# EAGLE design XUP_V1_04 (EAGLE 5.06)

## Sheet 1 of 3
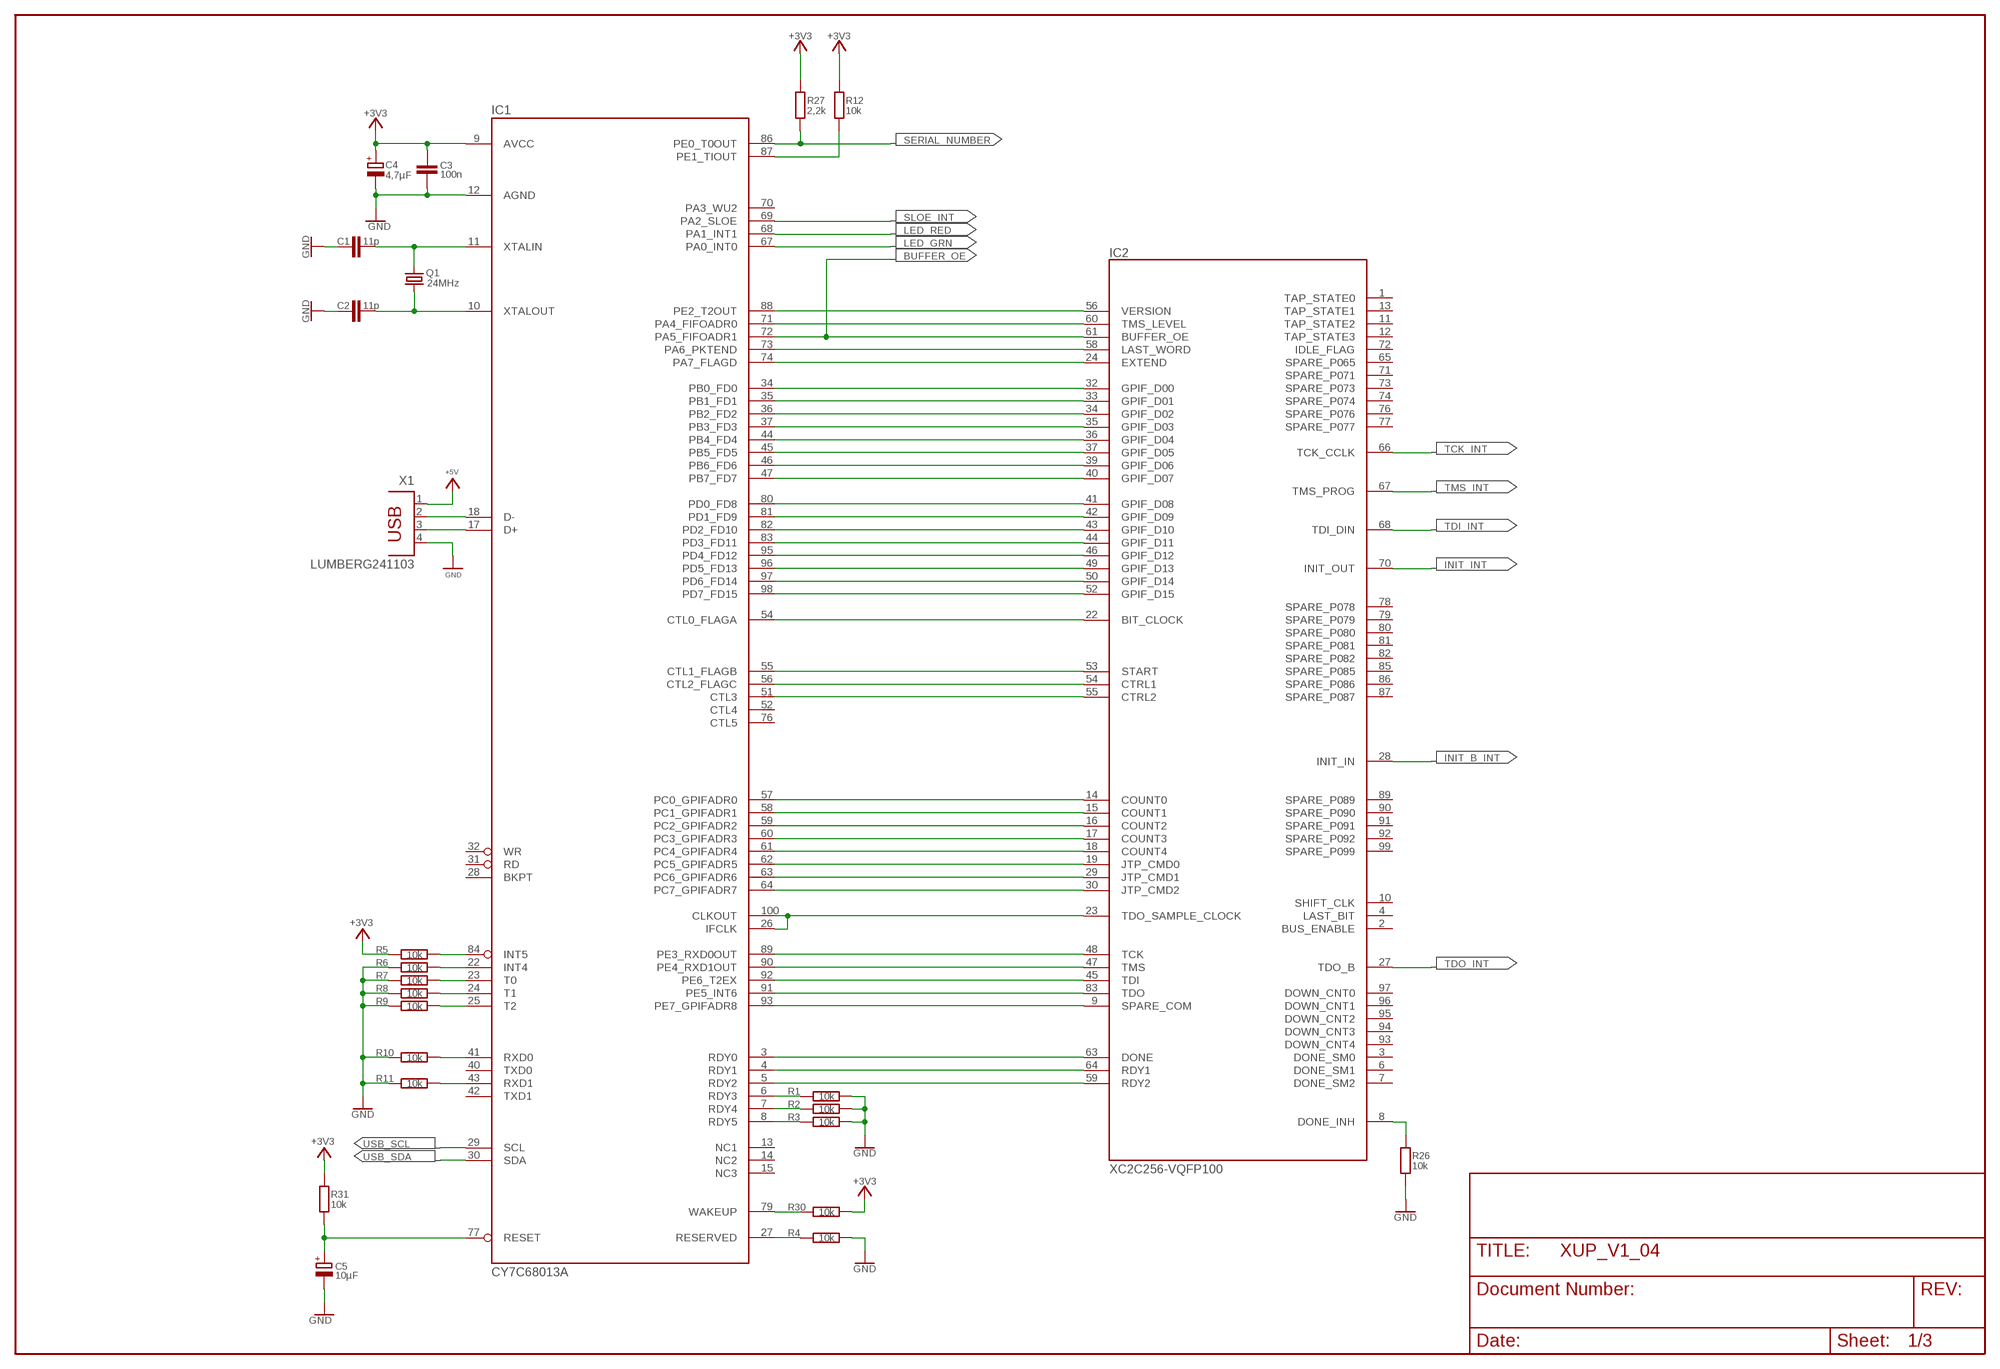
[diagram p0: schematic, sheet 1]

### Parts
C1  11p  C-EUALT  [0805ALT]
C2  11p  C-EUALT  [0805ALT]
C3  100n  C-EUC0603K  [C0603K]
C4  4,7µF  CPOL-EUB/3528-21R  [B/3528-21R]
C5  10µF  CPOL-EUB/3528-21R  [B/3528-21R]
IC1  CY7C68013A  [QFP100R]
IC2  XC2C256-VQFP100  [VQFP100]
Q1  24MHz  CRYTALHC49U-V  [HC49U-V]
R1  10k  R-EU_  [0805ALT]
R2  10k  R-EU_  [0805ALT]
R3  10k  R-EU_  [0805ALT]
R4  10k  R-EU_  [0805ALT]
R5  10k  R-EU_  [0805ALT]
R6  10k  R-EU_  [0805ALT]
R7  10k  R-EU_  [0805ALT]
R8  10k  R-EU_  [0805ALT]
R9  10k  R-EU_  [0805ALT]
R10  10k  R-EU_  [0805ALT]
R11  10k  R-EU_  [0805ALT]
R12  10k  R-EU_  [0805ALT]
R26  10k  R-EU_  [0805ALT]
R27  2,2k  R-EU_  [0805ALT]
R30  10k  R-EU_  [0805ALT]
R31  10k  R-EU_  [0805ALT]
X1  LUMBERG241103  [LUMBERG24110X]

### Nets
+3V3: C3.1 C4.+ IC1.9(AVCC) R5.1 R12.2 R27.2 R30.2 R31.2 ; also sheet 2,3
+5V: X1.1 ; also sheet 2
BUFFER_OE: IC1.72(PA5_FIFOADR1) IC2.61(BUFFER_OE) ; also sheet 3
GND: C1.1 C2.1 C3.2 C4.- C5.- IC1.12(AGND) R1.2 R2.2 R3.2 R4.2 R6.1 R7.1 R8.1 R9.1 R10.1 R11.1 R26.1 X1.4 ; also sheet 2,3
INIT_B_INT: IC2.28(INIT_IN) ; also sheet 3
INIT_INT: IC2.70(INIT_OUT) ; also sheet 3
LED_GRN: IC1.67(PA0_INT0) ; also sheet 2
LED_RED: IC1.68(PA1_INT1) ; also sheet 2
N$1: IC1.88(PE2_T2OUT) IC2.56(VERSION)
N$2: IC1.71(PA4_FIFOADR0) IC2.60(TMS_LEVEL)
N$3: IC1.18(D-) X1.2
N$4: IC1.73(PA6_PKTEND) IC2.58(LAST_WORD)
N$5: IC1.74(PA7_FLAGD) IC2.24(EXTEND)
N$6: IC1.34(PB0_FD0) IC2.32(GPIF_D00)
N$7: IC1.35(PB1_FD1) IC2.33(GPIF_D01)
N$8: IC1.36(PB2_FD2) IC2.34(GPIF_D02)
N$9: IC1.37(PB3_FD3) IC2.35(GPIF_D03)
N$10: IC1.44(PB4_FD4) IC2.36(GPIF_D04)
N$11: IC1.45(PB5_FD5) IC2.37(GPIF_D05)
N$12: IC1.46(PB6_FD6) IC2.39(GPIF_D06)
N$13: IC1.47(PB7_FD7) IC2.40(GPIF_D07)
N$14: IC1.80(PD0_FD8) IC2.41(GPIF_D08)
N$15: IC1.81(PD1_FD9) IC2.42(GPIF_D09)
N$16: IC1.82(PD2_FD10) IC2.43(GPIF_D10)
N$17: IC1.83(PD3_FD11) IC2.44(GPIF_D11)
N$18: IC1.95(PD4_FD12) IC2.46(GPIF_D12)
N$19: IC1.96(PD5_FD13) IC2.49(GPIF_D13)
N$20: IC1.97(PD6_FD14) IC2.50(GPIF_D14)
N$21: IC1.98(PD7_FD15) IC2.52(GPIF_D15)
N$22: IC1.54(CTL0_FLAGA) IC2.22(BIT_CLOCK)
N$23: IC1.55(CTL1_FLAGB) IC2.53(START)
N$24: IC1.56(CTL2_FLAGC) IC2.54(CTRL1)
N$25: IC1.51(CTL3) IC2.55(CTRL2)
N$26: IC1.57(PC0_GPIFADR0) IC2.14(COUNT0)
N$27: IC1.58(PC1_GPIFADR1) IC2.15(COUNT1)
N$28: IC1.59(PC2_GPIFADR2) IC2.16(COUNT2)
N$29: IC1.60(PC3_GPIFADR3) IC2.17(COUNT3)
N$30: IC1.61(PC4_GPIFADR4) IC2.18(COUNT4)
N$31: IC1.62(PC5_GPIFADR5) IC2.19(JTP_CMD0)
N$32: IC1.63(PC6_GPIFADR6) IC2.29(JTP_CMD1)
N$33: IC1.64(PC7_GPIFADR7) IC2.30(JTP_CMD2)
N$34: IC1.26(IFCLK) IC1.100(CLKOUT) IC2.23(TDO_SAMPLE_CLOCK)
N$35: IC1.89(PE3_RXD0OUT) IC2.48(TCK)
N$36: IC1.90(PE4_RXD1OUT) IC2.47(TMS)
N$37: IC1.92(PE6_T2EX) IC2.45(TDI)
N$38: IC1.91(PE5_INT6) IC2.83(TDO)
N$39: IC1.93(PE7_GPIFADR8) IC2.9(SPARE_COM)
N$40: IC1.3(RDY0) IC2.63(DONE)
N$41: IC1.4(RDY1) IC2.64(RDY1)
N$42: IC1.5(RDY2) IC2.59(RDY2)
N$43: IC1.84(INT5) R5.2
N$44: IC1.6(RDY3) R1.1
N$45: IC1.7(RDY4) R2.1
N$46: IC1.8(RDY5) R3.1
N$47: IC1.27(RESERVED) R4.1
N$48: IC1.22(INT4) R6.2
N$49: IC1.79(WAKEUP) R30.1
N$51: IC1.23(T0) R7.2
N$52: IC1.24(T1) R8.2
N$53: IC1.41(RXD0) R10.2
N$54: IC1.43(RXD1) R11.2
N$55: IC1.25(T2) R9.2
N$58: C1.2 IC1.11(XTALIN) Q1.2
N$59: C2.2 IC1.10(XTALOUT) Q1.1
N$60: IC1.87(PE1_TIOUT) R12.1
N$66: IC1.17(D+) X1.3
N$75: IC2.8(DONE_INH) R26.2
RST: C5.+ IC1.77(RESET) R31.1
SERIAL_NUMBER: IC1.86(PE0_T0OUT) R27.1 ; also sheet 2
SLOE_INT: IC1.69(PA2_SLOE) ; also sheet 3
TCK_INT: IC2.66(TCK_CCLK) ; also sheet 3
TDI_INT: IC2.68(TDI_DIN) ; also sheet 3
TDO_INT: IC2.27(TDO_B) ; also sheet 3
TMS_INT: IC2.67(TMS_PROG) ; also sheet 3
USB_SCL: IC1.29(SCL) ; also sheet 2
USB_SDA: IC1.30(SDA) ; also sheet 2
Unconnected: IC1.13(NC1) IC1.14(NC2) IC1.15(NC3) IC1.28(BKPT) IC1.31(RD) IC1.32(WR) IC1.40(TXD0) IC1.42(TXD1) IC1.52(CTL4) IC1.70(PA3_WU2) IC1.76(CTL5) IC2.1(TAP_STATE0) IC2.2(BUS_ENABLE) IC2.3(DONE_SM0) IC2.4(LAST_BIT) IC2.6(DONE_SM1) IC2.7(DONE_SM2) IC2.10(SHIFT_CLK) IC2.11(TAP_STATE2) IC2.12(TAP_STATE3) IC2.13(TAP_STATE1) IC2.65(SPARE_P065) IC2.71(SPARE_P071) IC2.72(IDLE_FLAG) IC2.73(SPARE_P073) IC2.74(SPARE_P074) IC2.76(SPARE_P076) IC2.77(SPARE_P077) IC2.78(SPARE_P078) IC2.79(SPARE_P079) IC2.80(SPARE_P080) IC2.81(SPARE_P081) IC2.82(SPARE_P082) IC2.85(SPARE_P085) IC2.86(SPARE_P086) IC2.87(SPARE_P087) IC2.89(SPARE_P089) IC2.90(SPARE_P090) IC2.91(SPARE_P091) IC2.92(SPARE_P092) IC2.93(DOWN_CNT4) IC2.94(DOWN_CNT3) IC2.95(DOWN_CNT2) IC2.96(DOWN_CNT1) IC2.97(DOWN_CNT0) IC2.99(SPARE_P099)

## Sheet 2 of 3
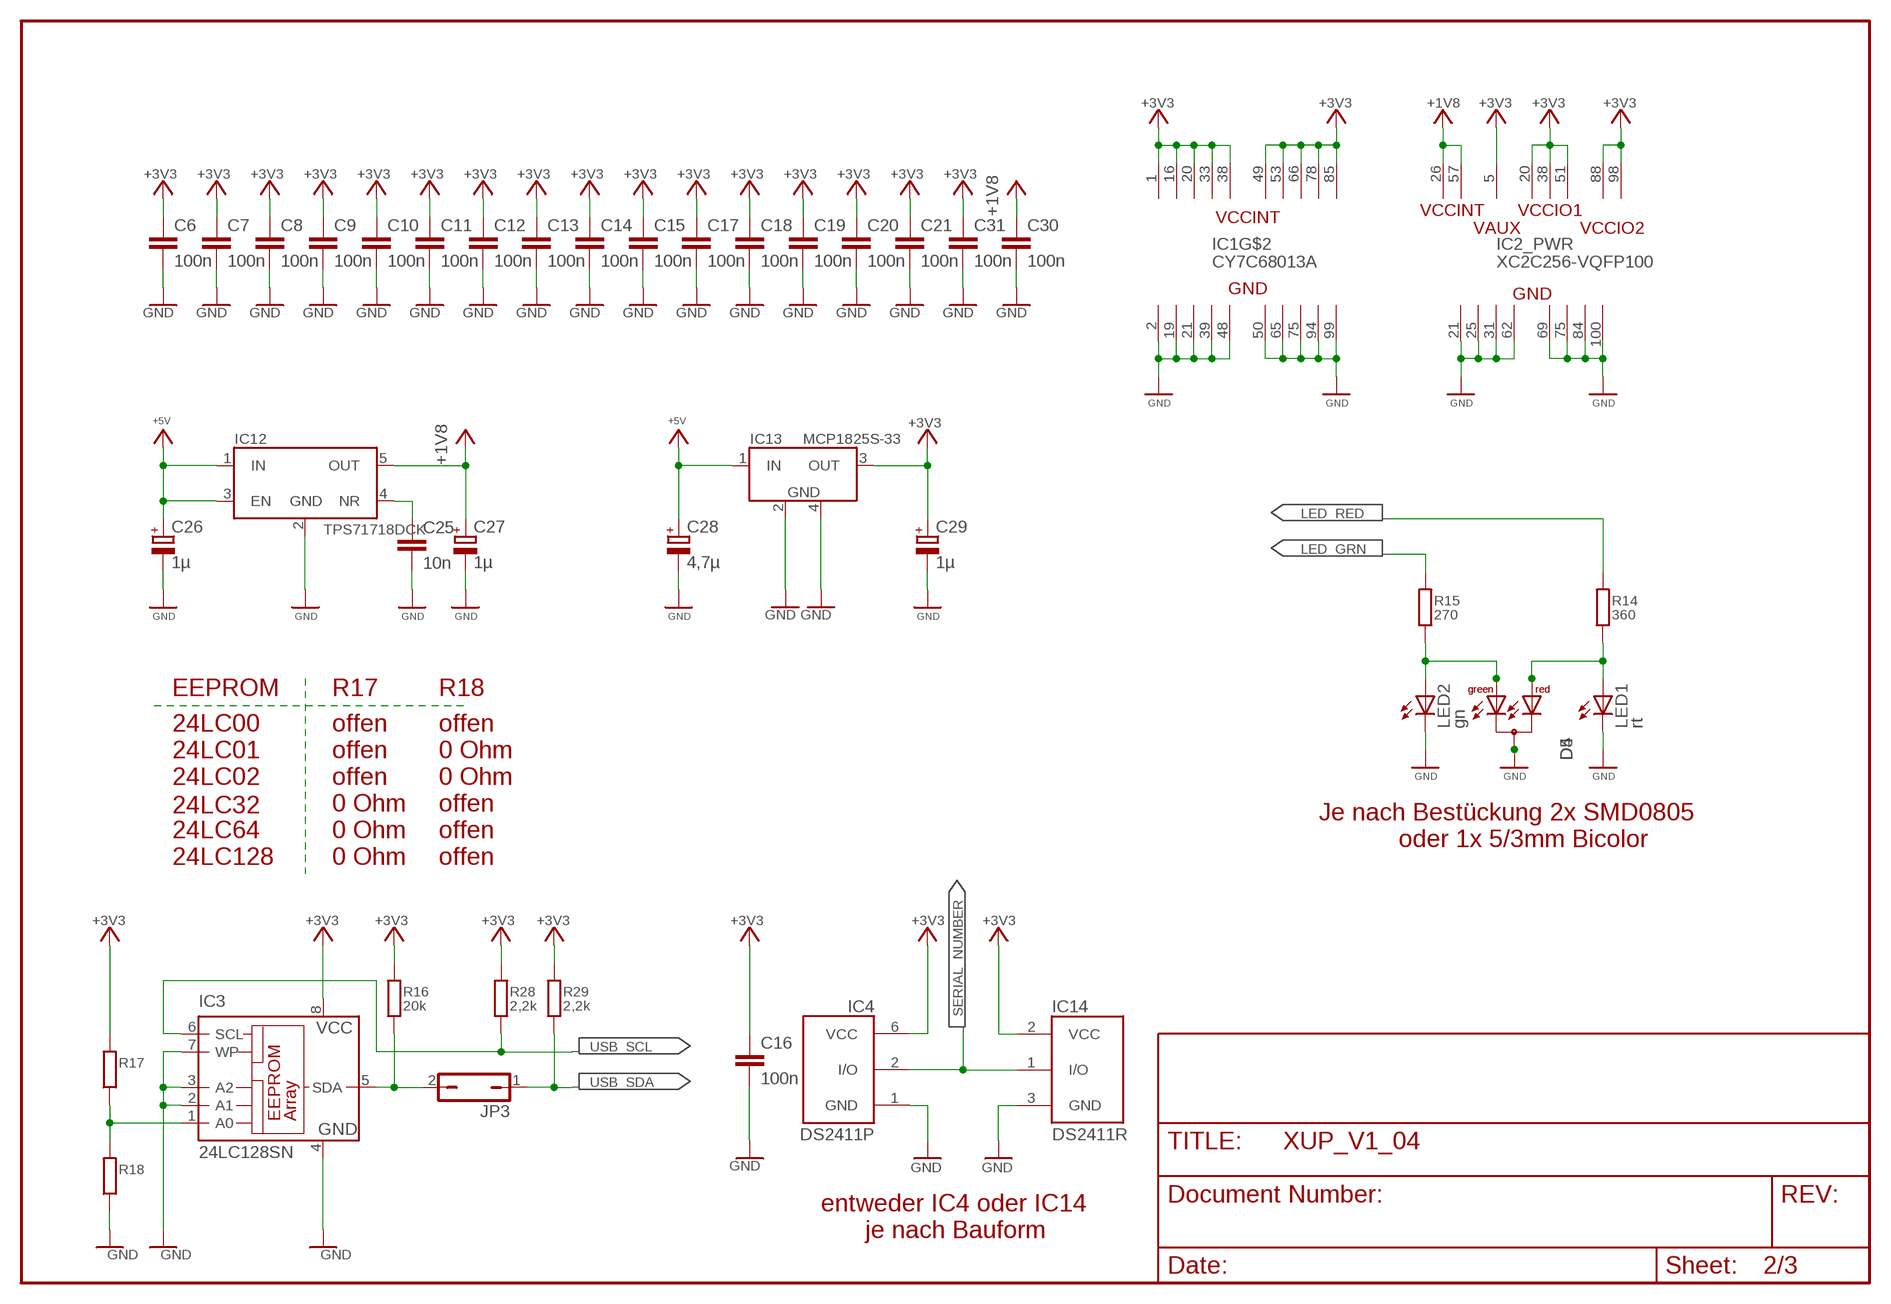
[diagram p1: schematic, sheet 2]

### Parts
C6  100n  C-EUC0603K  [C0603K]
C7  100n  C-EUC0603K  [C0603K]
C8  100n  C-EUC0603K  [C0603K]
C9  100n  C-EUC0603K  [C0603K]
C10  100n  C-EUC0603K  [C0603K]
C11  100n  C-EUC0603K  [C0603K]
C12  100n  C-EUC0603K  [C0603K]
C13  100n  C-EUC0603K  [C0603K]
C14  100n  C-EUC0603K  [C0603K]
C15  100n  C-EUC0603K  [C0603K]
C16  100n  C-EUC0603K  [C0603K]
C17  100n  C-EUC0603K  [C0603K]
C18  100n  C-EUC0603K  [C0603K]
C19  100n  C-EUC0603K  [C0603K]
C20  100n  C-EUC0603K  [C0603K]
C21  100n  C-EUC0603K  [C0603K]
C25  10n  C-EUALT  [0805ALT]
C26  1µ  CPOL-EUB/3528-21R  [B/3528-21R]
C27  1µ  CPOL-EUB/3528-21R  [B/3528-21R]
C28  4,7µ  CPOL-EUB/3528-21R  [B/3528-21R]
C29  1µ  CPOL-EUB/3528-21R  [B/3528-21R]
C30  100n  C-EUC0603K  [C0603K]
C31  100n  C-EUC0603K  [C0603K]
D4  DUOLED5MM  [DUOLED5MM]
D5  DUOLED5MM  [DUOLED5MM]
IC3  24LC128SN  [SO-08]
IC4  DS2411P  [TSOC6]
IC12  TPS71718DCK  [SC70-5L]
IC13  MCP1825S-33  [SOT223]
IC14  DS2411R  [SOT23]
JP3  JP1Q  [JP1]
LED1  rt  LEDCHIPLED_0805  [CHIPLED_0805]
LED2  gn  LEDCHIPLED_0805  [CHIPLED_0805]
R14  360  R-EU_  [0805ALT]
R15  270  R-EU_  [0805ALT]
R16  20k  R-EU_  [0805ALT]
R17  R-EU_  [0805ALT]
R18  R-EU_  [0805ALT]
R28  2,2k  R-EU_  [0805ALT]
R29  2,2k  R-EU_  [0805ALT]

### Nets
+1V8: C27.+ C30.1 IC2.26(VCCINT) IC2.57(VCCINT) IC12.5(OUT)
+3V3: C6.1 C7.1 C8.1 C9.1 C10.1 C11.1 C12.1 C13.1 C14.1 C15.1 C16.1 C17.1 C18.1 C19.1 C20.1 C21.1 C29.+ C31.1 IC1.1(+3V3) IC1.16(+3V3) IC1.20(+3V3) IC1.33(+3V3) IC1.38(+3V3) IC1.49(+3V3) IC1.53(+3V3) IC1.66(+3V3) IC1.78(+3V3) IC1.85(+3V3) IC2.5(VAUX) IC2.20(VCCIO) IC2.38(VCCIO) IC2.51(VCCIO) IC2.88(VCCIO) IC2.98(VCCIO) IC3.8(VCC) IC4.6(VCC) IC13.3(OUT) IC14.2(VCC) R16.2 R17.2 R28.2 R29.2 ; also sheet 1,3
+5V: C26.+ C28.+ IC12.1(IN) IC12.3(EN) IC13.1(IN) ; also sheet 1
GND: C6.2 C7.2 C8.2 C9.2 C10.2 C11.2 C12.2 C13.2 C14.2 C15.2 C16.2 C17.2 C18.2 C19.2 C20.2 C21.2 C25.2 C26.- C27.- C28.- C29.- C30.2 C31.2 D4.K(C) D5.K(C) IC1.2(GNA) IC1.19(GNA) IC1.21(GNA) IC1.39(GNA) IC1.48(GNA) IC1.50(GNA) IC1.65(GNA) IC1.75(GNA) IC1.94(GNA) IC1.99(GNA) IC2.21(GND) IC2.25(GND) IC2.31(GND) IC2.62(GND) IC2.69(GND) IC2.75(GND) IC2.84(GND) IC2.100(GND) IC3.2(A1) IC3.3(A2) IC3.4(GND) IC3.7(WP) IC4.1(GND) IC12.2(GND) IC13.2(GND) IC13.4(GND) IC14.3(GND) LED1.C LED2.C R18.1 ; also sheet 1,3
LED_GRN: R15.2 ; also sheet 1
LED_RED: R14.2 ; also sheet 1
N$56: IC3.1(A0) R17.1 R18.2
N$61: C25.1 IC12.4(NR)
N$63: IC3.5(SDA) JP3.2 R16.1
N$64: D4.AR D5.AR LED1.A R14.1
N$65: D4.AG D5.AG LED2.A R15.1
SERIAL_NUMBER: IC4.2(I/O) IC14.1(I/O) ; also sheet 1
USB_SCL: IC3.6(SCL) R28.1 ; also sheet 1
USB_SDA: JP3.1 R29.1 ; also sheet 1

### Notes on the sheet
- EEPROM | R17 | R18
- 24LC00 | offen | offen
- 24LC01 | offen | 0 Ohm
- 24LC02 | offen | 0 Ohm
- 24LC32 | 0 Ohm | offen
- Je nach Bestückung 2x SMD0805
- 24LC64 | 0 Ohm | offen
- oder 1x 5/3mm Bicolor
- 24LC128 | 0 Ohm | offen
- entweder IC4 oder IC14
- je nach Bauform

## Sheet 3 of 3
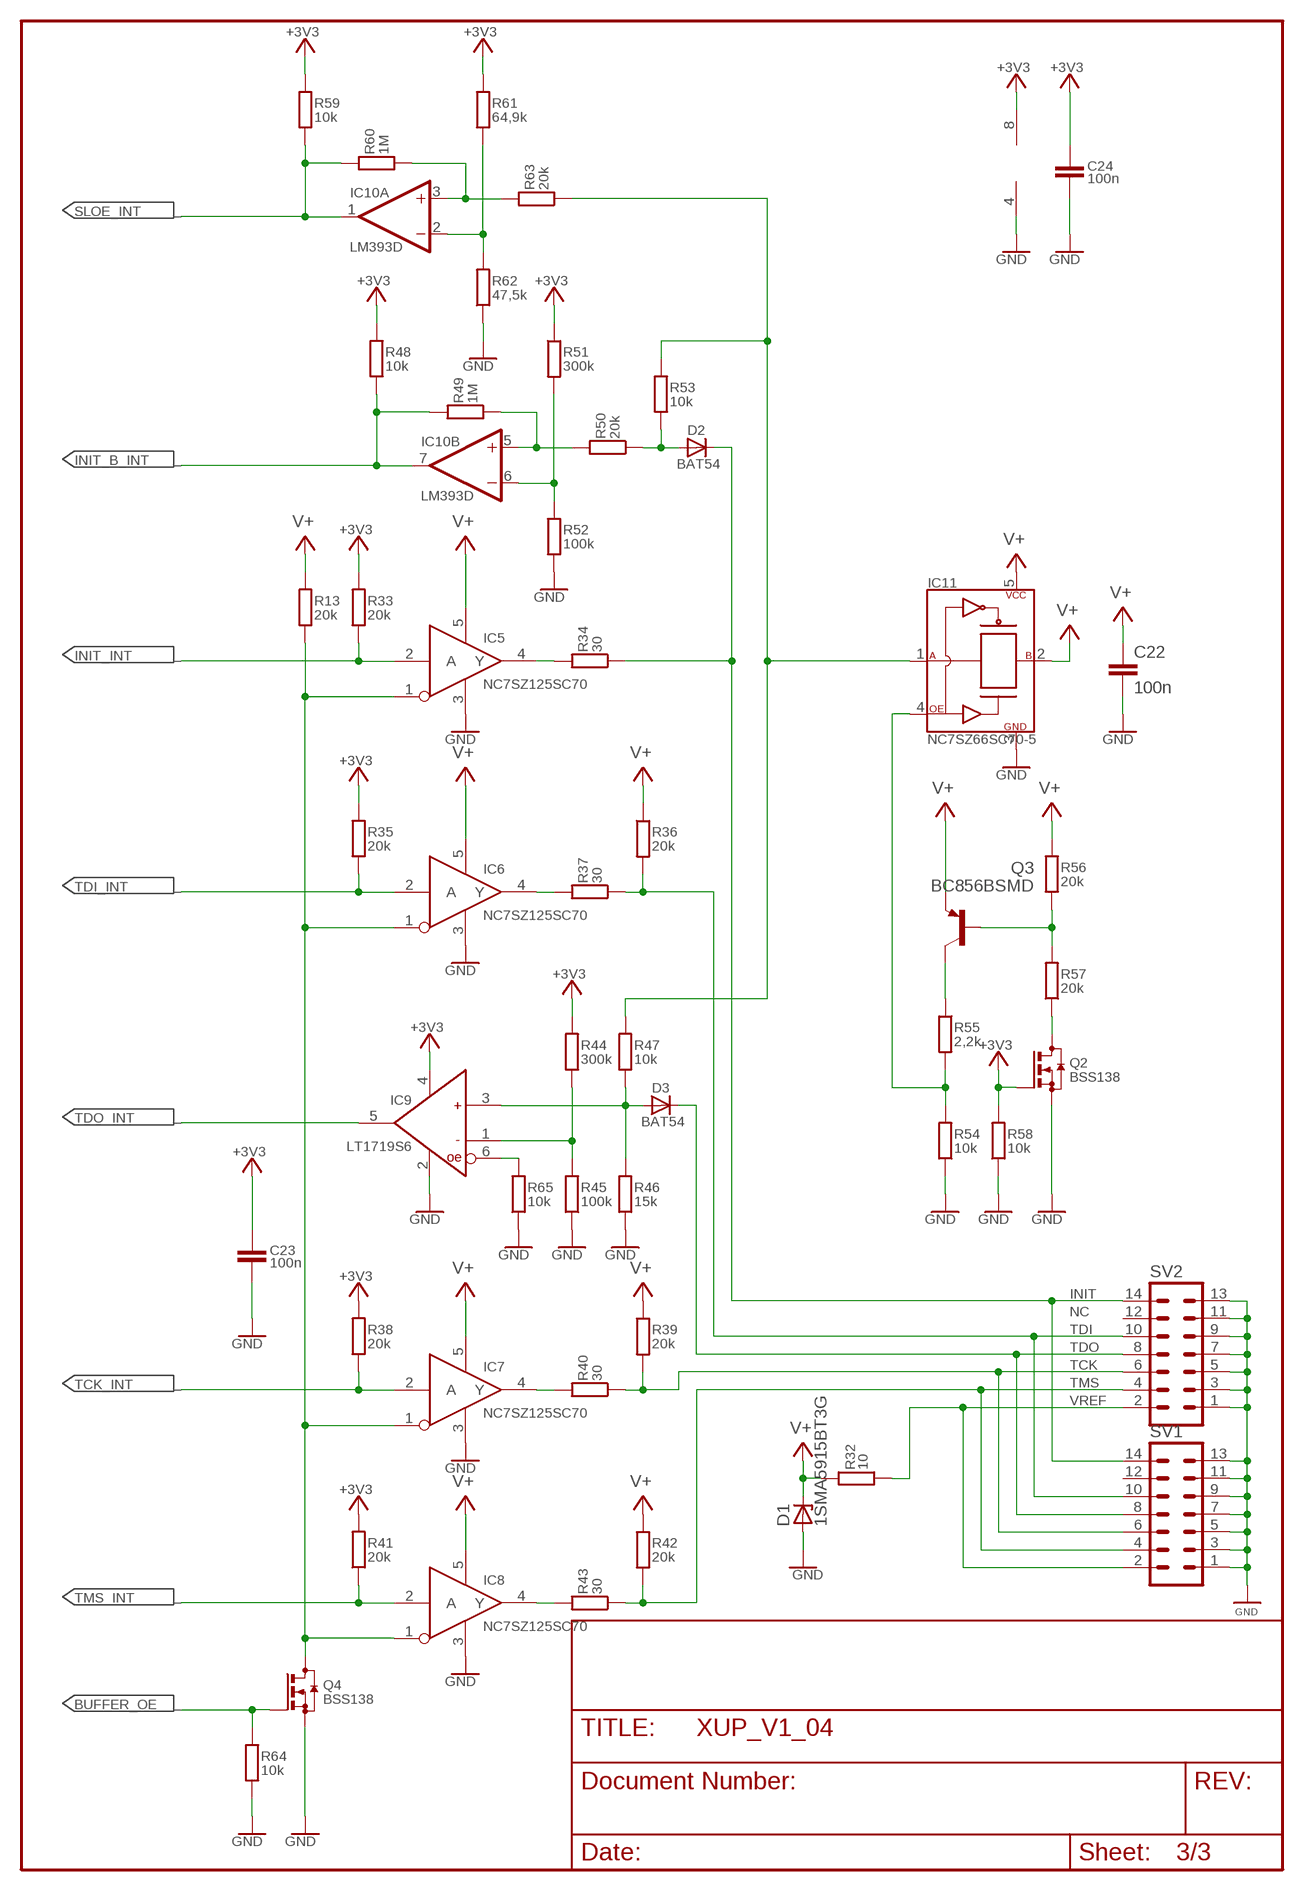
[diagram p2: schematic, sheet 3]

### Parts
C22  100n  C-EUC0603K  [C0603K]
C23  100n  C-EUC0603K  [C0603K]
C24  100n  C-EUC0603K  [C0603K]
D1  1SMA5915BT3G  ZENER-DIODESMB  [SMB]
D2  BAT54  DIODE-SOD323-W  [SOD323-W]
D3  BAT54  DIODE-SOD323-W  [SOD323-W]
IC5  NC7SZ125SC70  [SC70-5L]
IC6  NC7SZ125SC70  [SC70-5L]
IC7  NC7SZ125SC70  [SC70-5L]
IC8  NC7SZ125SC70  [SC70-5L]
IC9  LT1719S6  [SOT23-6]
IC10  LM393D  [SO08]
IC11  NC7SZ66SC70-5  [SOT23-5LSC70-5L]
Q2  BSS138  BSS123  [SOT23]
Q3  BC856BSMD  [SOT23-BEC]
Q4  BSS138  BSS123  [SOT23]
R13  20k  R-EU_  [0805ALT]
R32  10  R-EU_R2010  [R2010]
R33  20k  R-EU_  [0805ALT]
R34  30  R-EU_  [0805ALT]
R35  20k  R-EU_  [0805ALT]
R36  20k  R-EU_  [0805ALT]
R37  30  R-EU_  [0805ALT]
R38  20k  R-EU_  [0805ALT]
R39  20k  R-EU_  [0805ALT]
R40  30  R-EU_  [0805ALT]
R41  20k  R-EU_  [0805ALT]
R42  20k  R-EU_  [0805ALT]
R43  30  R-EU_  [0805ALT]
R44  300k  R-EU_  [0805ALT]
R45  100k  R-EU_  [0805ALT]
R46  15k  R-EU_  [0805ALT]
R47  10k  R-EU_  [0805ALT]
R48  10k  R-EU_  [0805ALT]
R49  1M  R-EU_  [0805ALT]
R50  20k  R-EU_  [0805ALT]
R51  300k  R-EU_  [0805ALT]
R52  100k  R-EU_  [0805ALT]
R53  10k  R-EU_  [0805ALT]
R54  10k  R-EU_  [0805ALT]
R55  2,2k  R-EU_  [0805ALT]
R56  20k  R-EU_  [0805ALT]
R57  20k  R-EU_  [0805ALT]
R58  10k  R-EU_  [0805ALT]
R59  10k  R-EU_  [0805ALT]
R60  1M  R-EU_  [0805ALT]
R61  64,9k  R-EU_  [0805ALT]
R62  47,5k  R-EU_  [0805ALT]
R63  20k  R-EU_  [0805ALT]
R64  10k  R-EU_  [0805ALT]
R65  10k  R-EU_  [0805ALT]
SV1  ML14L  [ML14L]
SV2  ML14L  [ML14L]

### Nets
+3V3: C23.1 C24.1 IC9.4(VCC) IC10.8(P:V+) Q2.1(G) R33.2 R35.2 R38.2 R41.2 R44.2 R48.2 R51.1 R58.2 R59.2 R61.2 ; also sheet 1,2
BUFFER_OE: Q4.1(G) R64.2 ; also sheet 1
GND: C22.2 C23.2 C24.2 D1.A IC5.3(GND) IC6.3(GND) IC7.3(GND) IC8.3(GND) IC9.2(GND) IC10.4(P:V-) IC11.3(GND) Q2.2(S) Q4.2(S) R45.1 R46.1 R52.2 R54.1 R58.1 R62.1 R64.1 R65.1 SV1.1 SV1.3 SV1.5 SV1.7 SV1.9 SV1.11 SV1.13 SV2.1 SV2.3 SV2.5 SV2.7 SV2.9 SV2.11 SV2.13 ; also sheet 1,2
INIT: D2.C R34.1 SV1.14 SV2.14
INIT_B_INT: IC10.7(B:OUT) R48.1 R49.2 ; also sheet 1
INIT_INT: IC5.2(A) R33.1 ; also sheet 1
N$50: Q3.C R55.1
N$67: D2.A R50.1 R53.1
N$76: IC5.4(Y) R34.2
N$77: IC10.5(B:+IN) R49.1 R50.2
N$78: IC6.4(Y) R37.2
N$79: IC10.6(B:-IN) R51.2 R52.1
N$80: D3.A IC9.3(+) R46.2 R47.1
N$81: Q2.3(D) R57.1
N$82: IC7.4(Y) R40.2
N$83: IC9.1(-) R44.1 R45.2
N$84: IC8.4(Y) R43.2
N$86: Q3.B R56.1 R57.2
N$87: IC9.6(OE) R65.2
N$89: IC11.4(OE) R54.2 R55.2
N$90: IC5.1(OE) IC6.1(OE) IC7.1(OE) IC8.1(OE) Q4.3(D) R13.1
N$92: IC10.3(A:+IN) R60.1 R63.2
N$93: IC10.2(A:-IN) R61.1 R62.2
SLOE_INT: IC10.1(A:OUT) R59.1 R60.2 ; also sheet 1
TCK: R39.2 R40.1 SV1.6 SV2.6
TCK_INT: IC7.2(A) R38.1 ; also sheet 1
TDI: R36.2 R37.1 SV1.10 SV2.10
TDI_INT: IC6.2(A) R35.1 ; also sheet 1
TDO: D3.C SV1.8 SV2.8
TDO_INT: IC9.5(Y) ; also sheet 1
TMS: R42.2 R43.1 SV1.4 SV2.4
TMS_INT: IC8.2(A) R41.1 ; also sheet 1
V+: C22.1 D1.C IC5.5(VCC) IC6.5(VCC) IC7.5(VCC) IC8.5(VCC) IC11.2(B) IC11.5(VCC) Q3.E R13.2 R32.1 R36.1 R39.1 R42.1 R56.2
VREF: R32.2 SV1.2 SV2.2
VREF_ENABLE: IC11.1(A) R47.2 R53.2 R63.1
Unconnected: SV1.12 SV2.12

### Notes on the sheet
- NC

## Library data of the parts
C1-C3 C6-C25 C30 C31 = rcl:C-EU: CAPACITOR, European symbol
C4 C5 C26-C29 = rcl:CPOL-EU: POLARIZED CAPACITOR, European symbol
D1 = diode:ZENER-DIODE: Z-Diode
D2 D3 = diode:DIODE-: DIODE
D4 D5 = led:DUOLED5MM: DUO LED 2 colors, 5 mm, round
IC1 = JEK-XILINX-USB-Kabel:CY7C68013A
IC2 = JEK-XILINX-USB-Kabel:XC2C256
IC3 = microchip:24*: Serial EEPROM I2C
IC4 IC14 = maxim:DS2411
IC5-IC8 = JEK-XILINX-USB-Kabel:NC7SZ125
IC9 = JEK-XILINX-USB-Kabel:LT1719S6
IC10 = linear:LM393: COMPARATOR
IC11 = JEK-XILINX-USB-Kabel:NC7SZ66
IC12 = JEK-XILINX-USB-Kabel:TPS717
IC13 = JEK-XILINX-USB-Kabel:MCP1825S-
JP3 = jumper:JP1Q: JUMPER
LED1 LED2 = led:LED: LED
Q1 = crystal:CRYTAL: CRYSTAL
Q2 Q4 = transistor-small-signal:BSS123: N-CHANNEL MOS FET
Q3 = transistor-pnp:BC856*: PNP Transistror
R1-R18 R26-R65 = rcl:R-EU_: RESISTOR, European symbol
SV1 SV2 = con-harting-ml:ML14: HARTING
X1 = con-berg:LUMBERG24110

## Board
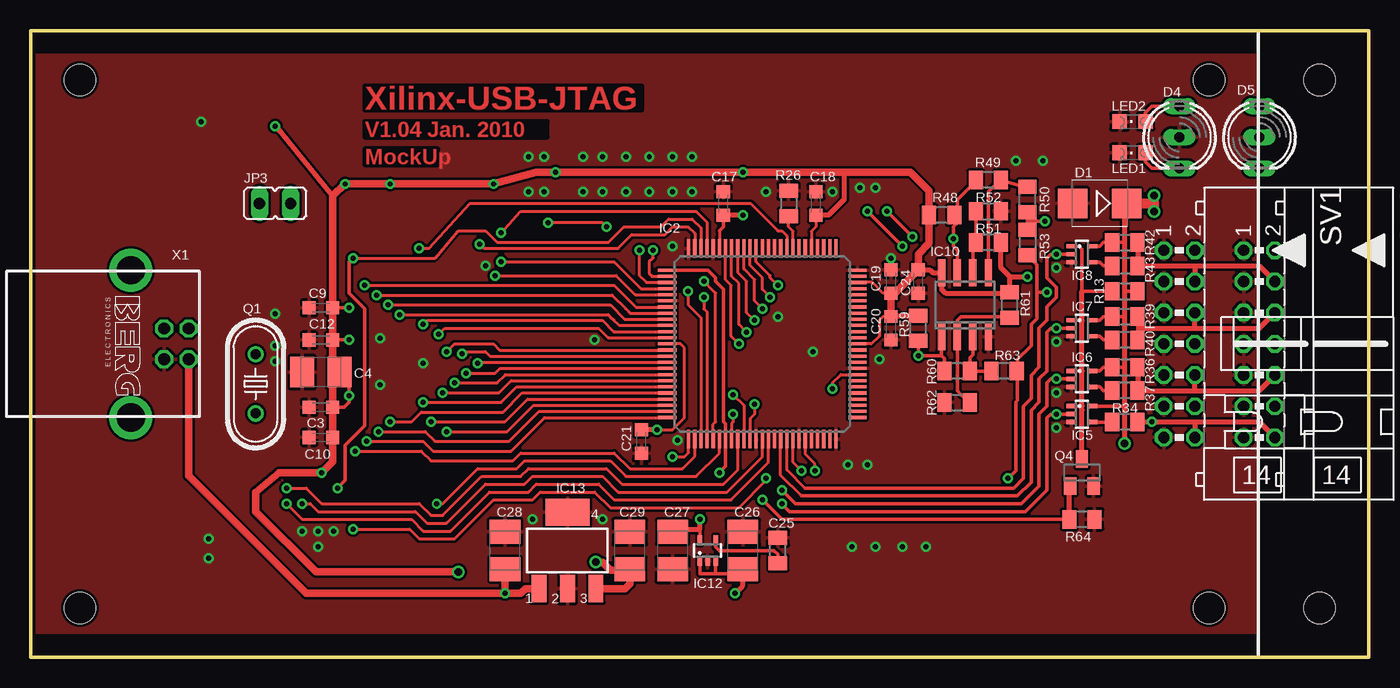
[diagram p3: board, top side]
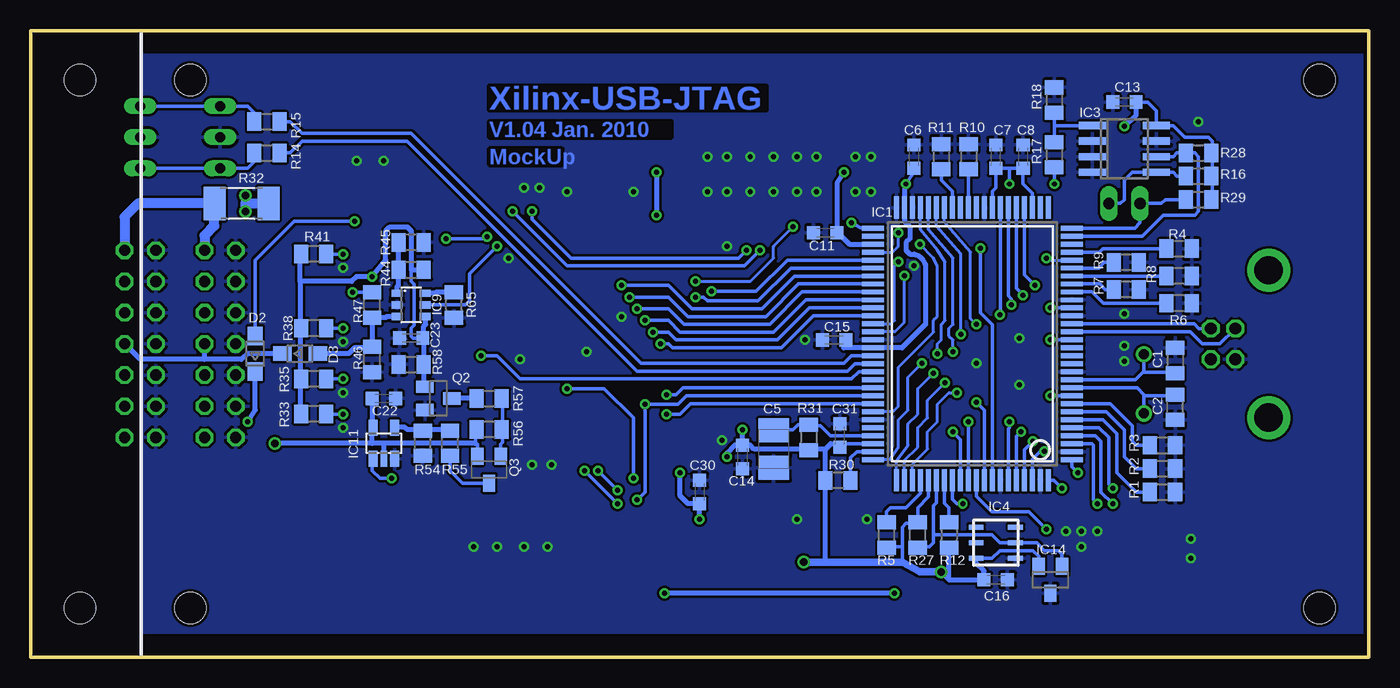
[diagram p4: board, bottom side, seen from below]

Size 109 x 51 mm. Coordinates in mm from the lower left corner, seen from the top.
Outline: 0,51 109,51 109,0 0,0 0,51
Copper layers (1+16): Top 0.035mm / dielectric 1.5mm / Bottom 0.035mm
Design rules "default": minimum track width 10mil, minimum drill 16mil, track to track 8mil, track to pad 8mil, pad to pad 8mil, via to via 8mil, smd to smd 8mil, copper to edge 10mil, drill to drill 8mil, minimum pad ring 10mil, minimum via ring 8mil, stop-mask expansion 4mil, vias tented up to drill 0mil, thermal gap 10mil
Holes 2.54 mm at 96,4 96,47 4,4 4,47 105,4 105,47

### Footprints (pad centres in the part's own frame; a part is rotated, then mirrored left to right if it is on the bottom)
0805ALT = smd 1.143 x 1.499: 1 -1.032,0; 2 1.032,0
C0603K = smd 1.05 x 1.08: 1 -0.954,0; 2 0.954,0
B/3528-21R = smd 1.95 x 2.5: + 1.525,0; - -1.525,0
SMB = smd 2.4 x 2.4: A 2.2,0; C -2.2,0
SOD323-W = smd 1.5 x 1.2: A 1.45,0; C -1.45,0
DUOLED5MM = drill 0.813 long: AG -2.54,0; AR 2.54,0; K 0,0
QFP100R = smd 0.4 x 1.8: 1 -9.425,-8.1; 2 -8.775,-8.1; 3 -8.125,-8.1; 4 -7.475,-8.1; 5 -6.825,-8.1; 6 -6.175,-8.1; 7 -5.525,-8.1; 8 -4.875,-8.1; 9 -4.225,-8.1; 10 -3.575,-8.1; 11 -2.925,-8.1; 12 -2.275,-8.1; 13 -1.625,-8.1; 14 -0.975,-8.1; 15 -0.325,-8.1; 16 0.325,-8.1; 17 0.975,-8.1; 18 1.625,-8.1; 19 2.275,-8.1; 20 2.925,-8.1; 21 3.575,-8.1; 22 4.225,-8.1; 23 4.875,-8.1; 24 5.525,-8.1; 25 6.175,-8.1; 26 6.825,-8.1; 27 7.475,-8.1; 28 8.125,-8.1; 29 8.775,-8.1; 30 9.425,-8.1; 51 9.425,8.1; 52 8.775,8.1; 53 8.125,8.1; 54 7.475,8.1; 55 6.825,8.1; 56 6.175,8.1; 57 5.525,8.1; 58 4.875,8.1; 59 4.225,8.1; 60 3.575,8.1; 61 2.925,8.1; 62 2.275,8.1; 63 1.625,8.1; 64 0.975,8.1; 65 0.325,8.1; 66 -0.325,8.1; 67 -0.975,8.1; 68 -1.625,8.1; 69 -2.275,8.1; 70 -2.925,8.1; 71 -3.575,8.1; 72 -4.225,8.1; 73 -4.875,8.1; 74 -5.525,8.1; 75 -6.175,8.1; 76 -6.825,8.1; 77 -7.475,8.1; 78 -8.125,8.1; 79 -8.775,8.1; 80 -9.425,8.1 | smd 1.8 x 0.4: 31 11.1,-6.175; 32 11.1,-5.525; 33 11.1,-4.875; 34 11.1,-4.225; 35 11.1,-3.575; 36 11.1,-2.925; 37 11.1,-2.275; 38 11.1,-1.625; 39 11.1,-0.975; 40 11.1,-0.325; 41 11.1,0.325; 42 11.1,0.975; 43 11.1,1.625; 44 11.1,2.275; 45 11.1,2.925; 46 11.1,3.575; 47 11.1,4.225; 48 11.1,4.875; 49 11.1,5.525; 50 11.1,6.175; 81 -11.1,6.175; 82 -11.1,5.525; 83 -11.1,4.875; 84 -11.1,4.225; 85 -11.1,3.575; 86 -11.1,2.925; 87 -11.1,2.275; 88 -11.1,1.625; 89 -11.1,0.975; 90 -11.1,0.325; 91 -11.1,-0.325; 92 -11.1,-0.975; 93 -11.1,-1.625; 94 -11.1,-2.275; 95 -11.1,-2.925; 96 -11.1,-3.575; 97 -11.1,-4.225; 98 -11.1,-4.875; 99 -11.1,-5.525; 100 -11.1,-6.175
VQFP100 = smd 1.5 x 0.254: 1 -7.75,6; 2 -7.75,5.5; 3 -7.75,5; 4 -7.75,4.5; 5 -7.75,4; 6 -7.75,3.5; 7 -7.75,3; 8 -7.75,2.5; 9 -7.75,2; 10 -7.75,1.5; 11 -7.75,1; 12 -7.75,0.5; 13 -7.75,0; 14 -7.75,-0.5; 15 -7.75,-1; 16 -7.75,-1.5; 17 -7.75,-2; 18 -7.75,-2.5; 19 -7.75,-3; 20 -7.75,-3.5; 21 -7.75,-4; 22 -7.75,-4.5; 23 -7.75,-5; 24 -7.75,-5.5; 25 -7.75,-6; 51 7.75,-6; 52 7.75,-5.5; 53 7.75,-5; 54 7.75,-4.5; 55 7.75,-4; 56 7.75,-3.5; 57 7.75,-3; 58 7.75,-2.5; 59 7.75,-2; 60 7.75,-1.5; 61 7.75,-1; 62 7.75,-0.5; 63 7.75,0; 64 7.75,0.5; 65 7.75,1; 66 7.75,1.5; 67 7.75,2; 68 7.75,2.5; 69 7.75,3; 70 7.75,3.5; 71 7.75,4; 72 7.75,4.5; 73 7.75,5; 74 7.75,5.5; 75 7.75,6 | smd 0.254 x 1.5: 26 -6,-7.75; 27 -5.5,-7.75; 28 -5,-7.75; 29 -4.5,-7.75; 30 -4,-7.75; 31 -3.5,-7.75; 32 -3,-7.75; 33 -2.5,-7.75; 34 -2,-7.75; 35 -1.5,-7.75; 36 -1,-7.75; 37 -0.5,-7.75; 38 0,-7.75; 39 0.5,-7.75; 40 1,-7.75; 41 1.5,-7.75; 42 2,-7.75; 43 2.5,-7.75; 44 3,-7.75; 45 3.5,-7.75; 46 4,-7.75; 47 4.5,-7.75; 48 5,-7.75; 49 5.5,-7.75; 50 6,-7.75; 76 6,7.75; 77 5.5,7.75; 78 5,7.75; 79 4.5,7.75; 80 4,7.75; 81 3.5,7.75; 82 3,7.75; 83 2.5,7.75; 84 2,7.75; 85 1.5,7.75; 86 1,7.75; 87 0.5,7.75; 88 0,7.75; 89 -0.5,7.75; 90 -1,7.75; 91 -1.5,7.75; 92 -2,7.75; 93 -2.5,7.75; 94 -3,7.75; 95 -3.5,7.75; 96 -4,7.75; 97 -4.5,7.75; 98 -5,7.75; 99 -5.5,7.75; 100 -6,7.75
SO-08 = smd 0.6 x 2.2: 1 -1.905,-2.6; 2 -0.635,-2.6; 3 0.635,-2.6; 4 1.905,-2.6; 5 1.905,2.6; 6 0.635,2.6; 7 -0.635,2.6; 8 -1.905,2.6
TSOC6 = smd 0.406 x 1.219: 1 -1.27,-1.6; 2 0,-1.6; 3 1.27,-1.6; 4 1.27,1.6; 5 0,1.6; 6 -1.27,1.6
SC70-5L = smd 0.35 x 0.8: 1 -0.65,-0.85; 2 0,-0.85; 3 0.65,-0.85; 4 0.65,0.85; 5 -0.65,0.85
SOT23-6 = smd 0.6 x 0.9: 1 -0.95,-1.15; 2 0,-1.15; 3 0.95,-1.15; 4 0.95,1.15; 5 0,1.15; 6 -0.95,1.15
SO08 = smd 0.6 x 2.2: 1 -1.905,-2.6; 2 -0.635,-2.6; 3 0.635,-2.6; 4 1.905,-2.6; 5 1.905,2.6; 6 0.635,2.6; 7 -0.635,2.6; 8 -1.905,2.6
SOT23-5LSC70-5L = smd 0.724 x 1.283: 1 -0.861,-1.262; 3 0.861,-1.262; 4 0.861,1.275; 5 -0.861,1.275 | smd 0.55 x 1.283: 2 0,-1.262
SOT223 = smd 1.219 x 2.235: 1 -2.311,-3.099; 2 0,-3.099; 3 2.311,-3.099 | smd 3.6 x 2.2: 4 0,3.099
SOT23 = smd 1 x 1.4: 1 -0.95,-1.1; 2 0.95,-1.1; 3 0,1.1
JP1 = drill 0.914 long: 1 0,-1.27; 2 0,1.27
CHIPLED_0805 = smd 1.2 x 1.2: A 0,-1.05; C 0,1.05
HC49U-V = drill 0.813 round: 1 -2.413,0; 2 2.413,0
SOT23-BEC = smd 1 x 1.4: B -0.95,-1.1; C 0,1.1; E 0.95,-1.1
R2010 = smd 1.8 x 2.7: 1 -2.2,0; 2 2.2,0
ML14L = drill 0.914 octagon: 1 -7.62,-1.27; 2 -7.62,1.27; 3 -5.08,-1.27; 4 -5.08,1.27; 5 -2.54,-1.27; 6 -2.54,1.27; 7 0,-1.27; 8 0,1.27; 9 2.54,-1.27; 10 2.54,1.27; 11 5.08,-1.27; 12 5.08,1.27; 13 7.62,-1.27; 14 7.62,1.27
LUMBERG24110X = drill 0.95 octagon: 1 1.25,4.71; 2 -1.25,4.71; 3 -1.25,2.71; 4 1.25,2.71 | drill 2.3 pad 3.5 round: GND@1 -6,0; GND@2 6,0

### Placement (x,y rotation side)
C1  15.78,24.15 270 bottom
C2  15.78,20.34 90 bottom
C3  23.64,20.34 180 top
C4  23.64,23.2 0 top
C5  48.48,16.93 90 bottom
C6  37.05,40.74 90 bottom
C7  30.38,40.74 90 bottom
C8  28.16,40.74 90 bottom
C9  23.64,28.44 180 top
C10  23.64,17.88 180 top
C11  44.28,34.55 180 bottom
C12  23.64,25.82 180 top
C13  19.91,45.19 180 bottom
C14  51.02,16.29 270 bottom
C15  43.56,25.82 180 bottom
C16  30.38,6.29 0 bottom
C17  56.42,36.93 90 top
C18  63.96,36.93 90 top
C19  70.07,30.58 90 top
C20  70.07,26.77 270 top
C21  49.75,17.56 270 top
C22  80.23,21.05 0 bottom
C23  78.01,25.98 180 bottom
C24  72.3,30.58 270 top
C25  60.87,8.67 90 top
C26  58.01,8.67 270 top
C27  52.29,8.67 90 top
C28  38.64,8.67 270 top
C29  48.8,8.67 270 top
C30  54.52,13.44 90 bottom
C31  43.09,18.04 90 bottom
D1  87.06,36.93 180 top
D2  90.71,24.71 90 bottom
D3  87.06,24.71 0 bottom
D4  93.57,42.33 270 top
D5  100.08,42.33 270 top
IC1  32.29,25.5 90 bottom
IC2  59.59,25.5 270 top
IC3  19.91,41.38 270 bottom
IC4  30.38,9.31 90 bottom
IC5  85.63,19.79 270 top
IC6  85.63,22.64 270 top
IC7  85.63,26.77 270 top
IC8  85.63,32.8 270 top
IC9  78.01,28.68 270 bottom
IC10  76.11,28.68 0 top
IC11  80.23,17.4 0 bottom
IC12  55.15,8.67 0 top
IC13  43.72,8.67 0 top
IC14  25.94,6.29 180 bottom
JP3  19.91,36.93 270 top
LED1  89.76,41.06 90 top
LED2  89.76,43.6 90 top
Q1  18.32,22.24 90 top
Q2  75.79,21.05 270 bottom
Q3  71.66,15.26 180 bottom
Q4  85.63,15.02 0 top
R1  16.81,13.44 0 bottom
R2  16.81,15.34 0 bottom
R3  16.81,17.24 0 bottom
R4  15.47,33.25 0 bottom
R5  39.27,9.94 90 bottom
R6  15.47,28.81 180 bottom
R7  19.75,29.92 180 bottom
R8  15.47,31.03 180 bottom
R9  19.75,32.14 180 bottom
R10  32.61,40.74 270 bottom
R11  34.83,40.74 270 bottom
R12  34.2,9.94 270 bottom
R13  89.12,29.79 0 top
R14  89.76,41.06 0 bottom
R15  89.76,43.6 0 bottom
R16  13.88,39.15 0 bottom
R17  25.62,40.9 270 bottom
R18  25.62,45.34 270 bottom
R26  61.74,36.93 270 top
R27  36.73,9.94 90 bottom
R28  13.88,41.06 0 bottom
R29  13.88,37.25 0 bottom
R30  43.24,14.39 180 bottom
R31  45.62,17.88 270 bottom
R32  91.82,36.93 180 bottom
R33  85.95,19.79 180 bottom
R34  89.12,19.15 180 top
R35  85.95,22.64 180 bottom
R36  89.12,23.59 0 top
R37  89.12,21.69 180 top
R38  85.95,26.77 180 bottom
R39  89.12,27.72 0 top
R40  89.12,25.82 180 top
R41  85.95,32.8 180 bottom
R42  89.12,33.76 0 top
R43  89.12,31.85 180 top
R44  78.01,31.53 0 bottom
R45  78.01,33.76 180 bottom
R46  81.19,24.23 90 bottom
R47  81.19,28.68 90 bottom
R48  74.2,35.98 180 top
R49  78.01,38.84 180 top
R50  81.19,37.25 90 top
R51  78.01,33.76 180 top
R52  78.01,36.3 0 top
R53  81.19,33.76 270 top
R54  77.06,17.4 90 bottom
R55  74.83,17.4 90 bottom
R56  71.66,18.52 180 bottom
R57  71.66,21.05 0 bottom
R58  78.01,23.83 0 bottom
R59  72.3,26.77 90 top
R60  75.47,23.28 180 top
R61  79.76,28.68 90 top
R62  75.47,20.74 0 top
R63  79.28,23.28 180 top
R64  85.63,11.21 180 top
R65  74.52,28.68 90 bottom
SV1  93.57,25.5 270 top
SV2  100.08,25.5 270 top
X1  8.16,25.5 270 top

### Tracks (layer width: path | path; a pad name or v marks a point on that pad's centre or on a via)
+1V8  (via drill 0.41)
  Top 0.305: IC2.26 55.18,31.5 55.78,30.9 55.78,30.58 56.42,29.95 56.42,19.15 56.59,18.98 IC2.57 56.59,15.52 v56.1,15.02 | 54.5,11.2 v54.52,11.21 | C27.+ 52.29,10.42 | 54.5,10.42 IC12.5
  Top 0.406: 54.5,11.2 54.5,10.42 52.29,10.42
  Bottom 0.406: v56.1,15.02 56.1,13.12 55.47,12.48 54.83,12.48 C30.1 v54.52,11.21
+3V3  (via drill 0.41, 0.61)
  Top 0.254: IC2.38 52.93,25.5 53.24,25.18 53.24,19.47 52.29,18.52 v51.02,18.52 | IC2.51 53.59,16.64 53.24,16.29 v52.29,16.29 | IC2.5 63.59,34.66 63.96,35.02 C18.1 | 56.09,34.7 IC2.20 | IC2.98 68.56,30.5 69.44,29.63 70.39,29.63 | IC2.88 68.48,25.5 69.12,26.14 69.12,27.41 69.44,27.72 70.39,27.72
  Top 0.305: C12.1 v25.94,25.82 | C3.1 25.54,20.34 25.94,20.74 v25.94,21.29 25.94,22.96 25.7,23.2 C4.+ | C9.1 v25.94,28.44 | 56.09,34.7 56.42,35.02 C17.1 | v51.02,18.52 | 64.99,35.98 64.91,35.98
  Top 0.406: 64.91,35.98 C18.1 | R51.1 79.04,31.69 79.76,30.98 | 79.76,30.98 v81.19,30.98 | 79.76,30.98 R61.2 79.92,29.63 74.52,29.63 74.2,29.95 IC10.8 74.2,31.29 73.49,31.29 73.25,31.53 C24.1 | 70.39,29.63 C19.1 | 70.39,27.72 C20.1 70.07,27.8 R59.2 | v51.02,18.52 C21.1 | 20.38,42.72 | 20.38,42.72 v19.91,43.2 | 24.59,37.56 20.38,42.72 | 64.99,35.98 66.26,37.25 66.26,39.47 | v58.01,35.98 C17.1 | 73.17,37.09
  Top 0.61: C24.1 70.39,29.63 | C19.1 70.07,27.8 | v46.02,7.72 46.58,7.72 47.21,7.09 48.8,7.09 | v34.83,6.93 24.19,6.93 23.24,6.93 18.32,11.85 18.32,13.44 20.23,15.02 v23.72,15.02 24.59,15.9 C10.1 C3.1 C12.1 C9.1 24.59,37.56 v25.62,38.52 v29.27,38.52 v37.69,38.52 41.18,39.47 v42.77,39.47 v58.01,39.47 66.26,39.47 71.66,39.47 73.17,37.96 73.17,37.09 R48.2 73.17,33.68 72.3,32.8 C24.1 | IC13.3 48.4,5.57 48.8,5.97 48.8,7.09 | 48.8,7.09 C29.+
  Bottom 0.305: IC1.38 30.66,37.92 30.38,38.2 C7.1 29.27,39.79 | IC1.33 27.41,37.77 28.16,38.52 C8.1 29.27,39.79 | C15.1 42.45,25.18 42.76,25.18 | IC1.78 43.09,17.38 C31.1 | 45.62,16.93 R31.2 | C6.1 37.05,39.47 v37.69,38.52 | IC1.85 35.87,13.04 36.73,12.16 R27.2 36.73,10.89 37.69,10.89 38.01,10.58 38.01,8.99 | v29.27,38.52 29.27,39.79 | R5.1 39.27,8.99 38.01,8.99 | 18.64,45.19 18,45.19 17.31,44.49 IC3.8 15.94,43.28 14.99,42.33 13.08,42.33 12.76,42.01 12.76,41.06 | IC1.16 v25.93,25.82 v25.94,25.82 | 25.92,21.27 IC1.9 | IC1.1 24.19,15.49 v23.72,15.02 | IC1.20 25.93,28.43 v25.94,28.44 | 78.01,31.53 78.01,30.58 77.77,30.34 77.77,27.01 78.01,26.77 78.01,26.14 77.85,25.98 77.14,25.98 | 18.64,45.19 C13.1 | C13.1 18.64,45.19 | C14.1 | 38.01,7.72 38.01,8.99 | 12.76,41.06 R28.2 | 12.76,41.06 12.76,39.15 | 12.76,39.15 R16.2 | R29.2 12.76,37.25 12.76,39.15 | IC14.2 26.89,8.19 27.37,8.67 30.07,8.67 30.7,8.04 IC4.6 | v25.62,38.52 R17.2 | R30.2
  Bottom 0.406: 42.76,25.18 IC1.66 38.01,25.18 36.1,27.09 36.1,31.85 arc-67 37.05,32.8 37.37,32.8 37.69,33.12 37.69,33.76 37.37,34.07 37.37,35.02 37.81,35.47 IC1.49 37.81,38.07 v37.69,38.52 | 43.09,17.38 43.83,17.38 44.28,16.93 | 44.28,16.93 45.62,16.93 50.07,16.93 50.39,17.24 C14.1 51.66,17.24 52.29,16.61 v52.29,16.29 | v19.91,43.2 18.95,44.15 C13.1 | v25.94,21.29 25.92,21.27 | R44.2 78.01,31.53 78.01,34.71 78.33,35.02 79.76,35.02 80.07,34.71 80.07,32.33 v81.19,30.98 82.45,30.98 82.85,30.58 87.06,30.58 | 76.98,25.98 R58.2 76.98,22.17 76.89,22.08 Q2.1 | 76.98,25.98 C23.1 77.14,25.98 | 76.98,25.98 | 76.98,25.98 76.98,26.93 76.82,27.09 76.82,27.72 76.82,27.73 IC9.4 | 77.14,25.98 | 44.28,16.93 R30.2 44.28,14.31 | C14.1 v51.02,18.52 | 44.28,14.31 | 44.28,7.72 44.28,14.31 | 34.2,6.29 32.45,6.29 | v34.83,6.93 34.2,6.29 | 32.45,6.29 | 32.45,6.29 C16.1 31.34,7.01 31.98,7.65 IC4.6 | 34.2,6.29 R12.2 | R41.2 87.06,32.8 87.06,30.58 | 87.06,30.58 87.06,26.77 | 87.06,26.77 R38.2 | 87.06,26.77 87.06,22.64 | R33.2 87.06,19.79 87.06,22.64 | 87.06,22.64 R35.2 | v58.01,39.47 v58.01,35.98 | IC1.53 42.32,33.62 43,34.31 C11.1 43.32,38.6 v42.77,39.47
  Bottom 0.61: v46.02,7.72 44.28,7.72 38.01,7.72 36.58,6.93 35.47,6.93 v34.83,6.93
+5V  (via drill 0.41)
  Top 0.305: IC12.1 54.5,6.77 56.1,6.77 | 58.01,7.09 58.01,6.77 56.1,6.77 | IC12.3 55.8,6.77 56.1,6.77
  Top 0.406: v57.37,5.18 58.01,5.82 58.01,7.09 C26.+
  Top 0.61: v38.64,5.18 C28.+ | IC13.1 40.3,5.57 39.91,5.18 v38.64,5.18 | v38.64,5.18 22.45,5.18 12.87,14.76 X1.1
  Bottom 0.406: v38.64,5.18 v57.37,5.18
BUFFER_OE  (via drill 0.41)
  Top 0.254: IC2.61 58.59,19.42 58.96,19.79 v58.96,20.58
  Top 0.305: v59.59,12.8 61.18,11.21 R64.2
  Top 0.406: 84.68,11.21 R64.2 84.6,13.92 Q4.1
  Bottom 0.305: IC1.72 55.56,21.27 56.26,20.58 v58.96,20.58 58.96,13.44 v59.59,12.8
GND  (via drill 0.41)
  Bottom 0.305: C23.2 | C23.2
  other vias: 28.48,22.17 19.91,25.34 19.91,24.07 19.91,27.96 52.29,33.44 52.69,17.64 40.55,37.88 41.81,37.88 48.48,37.88 50.39,37.88 83.57,31.69 83.57,25.66 83.57,21.53 83.57,18.67 60.87,27.72 40.86,11.21 46.58,11.21 63.72,24.86 63.72,24.86 66.9,8.99 68.8,8.99 71.03,8.99 31.97,23.91 28.48,25.98 14.51,9.62 14.51,8.04 72.93,8.99 80.23,40.42 82.45,40.42 13.88,43.6 23.4,10.26 22.13,10.26 23.4,8.99 24.67,10.26 69.12,24.23 70.07,32.48 67.53,38.2 59.91,37.88 65.31,37.88 46.58,37.88 44.99,37.88 52.29,37.88 53.88,37.88 68.8,38.2 46.58,40.74 48.48,40.74 50.39,40.74 52.29,40.74 53.88,40.74 44.99,40.74 41.81,40.74 40.55,40.74 66.58,15.66 68.17,15.66 45.94,25.82 37.05,31.85
  pour Bottom: 100,2 100,49 0,49 0,2
  pour Top: 0,49 0,2 100,2 100,49
INIT  (via drill 0.41)
  Top 0.406: R34.1 v91.34,19.15 94.84,19.15 | 94.84,19.15 100.08,19.15 SV2.14 | SV2.14 | 94.84,19.15 SV1.14
  Bottom 0.406: D2.C 90.71,20.1 v91.34,19.15
INIT_B_INT  (via drill 0.41)
  Top 0.254: 75.47,35.34 R48.1 | R49.2 77.06,38.2 | IC2.28 50.15,30.5 49.59,31.06 v49.59,33.12
  Top 0.305: R49.2 77.06,38.84 75.47,37.25 75.47,35.34 75.15,35.02 v75.15,34.07 75.15,33.44 75.47,33.12 IC10.7 | v71.82,34.23 71.18,34.87 v69.75,36.3
  Bottom 0.305: v49.59,33.12 50.86,31.85 65.31,31.85 v69.75,36.3 | v71.82,34.23 71.98,34.07 v75.15,34.07
INIT_INT  (via drill 0.41)
  Top 0.254: IC2.70 63.09,16.52 63.88,15.74 v63.88,15.18
  Top 0.305: IC5.2 v83.57,19.79 83.09,19.79 82.77,19.47 | 82.77,19.47 82.77,18.2 | 82.77,19.47 82.77,13.59 81.03,11.85 61.82,11.85 | 61.82,11.85 | v61.18,12.48 61.82,11.85
  Bottom 0.305: v83.57,19.79 R33.1 | v61.18,12.48 v63.88,15.18
LED_GRN
  Bottom 0.305: IC1.67 42.16,24.52 42.77,23.91 59.28,23.91 78.01,42.64 86.9,42.64 87.85,43.6 R15.2
LED_RED
  Bottom 0.305: IC1.68 41.85,23.88 42.45,23.28 59.59,23.28 78.33,42.01 86.9,42.01 87.85,41.06 R14.2
N$1  (via drill 0.41)
  Top 0.254: v33.08,12.48 33.56,12.48 36.42,15.34 39.59,15.34 40.23,15.97 47.21,15.97 48.48,14.71 54.2,14.71 56.09,16.6 IC2.56
  Bottom 0.305: IC1.88 33.91,12.84 33.56,12.48 v33.08,12.48
N$2  (via drill 0.41)
  Top 0.254: IC2.60 58.09,20.49 v57.21,21.37
  Bottom 0.305: IC1.71 55.87,21.93 56.42,21.37 v57.21,21.37
N$3
  Bottom 0.305: IC1.18 14.23,27.12 13.86,26.75 X1.2
N$4  (via drill 0.41)
  Top 0.254: IC2.58 57.09,19.03 57.21,19.15 v57.21,19.79
  Bottom 0.305: IC1.73 55.26,20.62 56.1,19.79 v57.21,19.79
N$5  (via drill 0.41)
  Top 0.254: IC2.24 54.09,34.49 53.56,35.02 52.29,35.02 51.66,34.39 48.96,34.39 47.85,33.28 36.89,33.28 v36.58,33.6
  Bottom 0.254: IC1.74 38.77,19.98 38.32,20.42 38.32,23.59 35.94,25.98 | 35.94,25.98 | 35.94,25.98 35.47,26.45 35.47,27.41 35.15,27.72 35.15,31.85 35.47,32.48 v36.58,33.6
N$6  (via drill 0.41)
  Top 0.254: v27.21,30.26 47.53,30.26 49.29,28.5 IC2.32
  Bottom 0.305: IC1.34 28.07,31.12 v27.21,30.26
N$7  (via drill 0.41)
  Top 0.254: v28.16,29.47 47.37,29.47 48.48,28.36 | 48.48,28.36 48.8,28.04 | IC2.33 48.84,28 48.48,28.36
  Bottom 0.305: IC1.35 28.71,30.02 v28.16,29.47
N$8  (via drill 0.41)
  Top 0.254: v29.11,28.68 47.21,28.68 48.39,27.5 IC2.34
  Bottom 0.305: IC1.36 29.36,29.4 29.11,29.15 v29.11,28.68
N$9  (via drill 0.41)
  Top 0.254: v30.07,27.88 47.05,27.88 47.37,27.56 | 47.37,27.56 47.53,27.41 | IC2.35 47.94,27 47.37,27.56
  Bottom 0.305: IC1.37 30.02,27.93 v30.07,27.88
N$10  (via drill 0.41)
  Top 0.254: IC2.36 47.48,26.5 46.58,27.41 32.29,27.41 v31.97,27.09
  Bottom 0.254: IC1.44 34.56,35.39 32.45,32.96 32.45,27.56 v31.97,27.09
N$11  (via drill 0.41)
  Top 0.254: IC2.37 47.03,26 46.26,26.77 33.72,26.77 v33.24,26.29
  Bottom 0.254: IC1.45 35.22,35.09 33.24,32.8 v33.24,26.29
N$12  (via drill 0.41)
  Top 0.254: IC2.39 38.19,25 37.69,25.5 34.51,25.5 v33.88,24.86
  Bottom 0.254: IC1.46 35.87,34.79 33.88,32.48 33.88,27.09 34.2,26.77 34.2,26.14 33.88,25.82 v33.88,24.86
N$13  (via drill 0.41)
  Top 0.254: IC2.40 37.42,24.5 37.05,24.86 35.31,24.86 v35.15,24.71
  Bottom 0.254: v35.15,24.71 35.15,25.5 34.83,25.82 34.83,27.09 34.51,27.41 34.51,32.17 35.15,33.12 36.52,34.8 IC1.47
N$14  (via drill 0.41)
  Top 0.254: IC2.41 36.51,24 v36.42,23.91
  Bottom 0.254: IC1.80 39.02,16.07 38.32,17.09 38.32,19.31 37.53,20.1 37.53,22.8 v36.42,23.91
N$15  (via drill 0.41)
  Top 0.254: v35.47,23.12 37.85,23.12 38.23,23.5 IC2.42
  Bottom 0.254: IC1.81 38.47,15.99 37.53,17.24 37.53,18.99 36.73,19.79 36.73,21.85 v35.47,23.12
N$16  (via drill 0.41)
  Top 0.254: v34.51,22.32 38.01,22.32 38.68,23 IC2.43
  Bottom 0.254: IC1.82 37.81,16.01 36.73,17.09 36.73,18.67 35.94,19.47 35.94,20.9 v34.51,22.32
N$17  (via drill 0.41)
  Top 0.254: v33.56,21.53 38.16,21.53 39.13,22.5 IC2.44
  Bottom 0.254: IC1.83 37.16,15.7 35.94,16.93 35.94,18.36 35.15,19.15 35.15,20.58 34.2,21.53 v33.56,21.53
N$18  (via drill 0.41)
  Top 0.254: IC2.46 40.04,21.5 38.48,19.94 31.81,19.94 31.02,19.15 v29.27,19.15
  Bottom 0.305: v29.27,19.15 29.27,18.67 29.36,18.58 IC1.95
N$19  (via drill 0.41)
  Top 0.254: v28.32,18.36 32.13,18.36 32.92,17.56 38.96,17.56 41.4,20 IC2.49
  Bottom 0.305: IC1.96 28.71,17.96 v28.32,18.36
N$20  (via drill 0.41)
  Top 0.254: v27.37,17.56 31.97,17.56 32.77,16.77 39.12,16.77 41.85,19.5 IC2.50
  Bottom 0.305: IC1.97 28.07,16.87 v27.37,17.56
N$21  (via drill 0.41)
  Top 0.254: IC2.52 54.09,16.35 53.09,15.34 48.8,15.34 47.53,16.61 39.91,16.61 39.27,15.97 32.61,15.97 31.81,16.77 v26.42,16.77
  Bottom 0.305: IC1.98 27.41,16.09 26.73,16.77 v26.42,16.77
N$22  (via drill 0.41)
  Top 0.254: IC2.22 55.09,35.4 54.2,36.3 39.91,36.3 38.64,34.87 v38.32,34.55
  Bottom 0.254: IC1.54 38.78,32.98 38.32,33.44 v38.32,34.55
N$23  (via drill 0.41)
  Top 0.254: v53.56,29.79 53.56,28.68 54.59,27.64 IC2.53
  Bottom 0.305: IC1.55 47.37,32.33 49.91,29.79 v53.56,29.79
N$24  (via drill 0.41)
  Top 0.254: v54.83,29.31 54.83,28.36 55.09,28.09 IC2.54
  Bottom 0.305: IC1.56 47.07,31.68 49.75,28.99 53.88,28.99 54.2,29.31 v54.83,29.31
N$25  (via drill 0.41)
  Top 0.254: 55.59,29.82 v54.83,30.58 | IC2.55 55.59,18.96 55.78,19.15 55.78,29.63 55.59,29.82 | 55.59,29.82 | v42.13,35.34 46.58,35.34 v46.9,35.02
  Bottom 0.254: v54.83,30.58 50.39,30.58 48.48,32.48 48.48,33.44 v46.9,35.02
  Bottom 0.305: IC1.51 40.45,34.92 40.47,34.95 41.42,34.95 v42.13,35.34
N$26  (via drill 0.41)
  Top 0.254: IC2.14 59.09,32.19 60.23,31.06 60.23,30.9 v60.87,30.26
  Bottom 0.305: IC1.57 46.77,31.02 49.44,28.36 55.15,28.36 57.05,30.26 v60.87,30.26
N$27  (via drill 0.41)
  Top 0.254: IC2.15 58.59,31.9 59.59,30.9 59.59,29.95 v60.23,29.31
  Bottom 0.305: IC1.58 46.47,30.38 49.12,27.72 55.47,27.72 57.05,29.31 v60.23,29.31
N$28  (via drill 0.41)
  Top 0.254: IC2.16 58.09,31.6 58.96,30.74 58.96,28.99 v59.59,28.36
  Bottom 0.305: IC1.59 46.16,29.73 48.8,27.09 55.78,27.09 57.05,28.36 v59.59,28.36
N$29  (via drill 0.41)
  Top 0.254: IC2.17 57.59,31.31 58.33,30.58 58.33,28.04 v58.96,27.41
  Bottom 0.305: IC1.60 45.86,29.07 48.48,26.45 56.1,26.45 57.05,27.41 v58.96,27.41
N$30  (via drill 0.41)
  Top 0.254: IC2.18 57.09,31.02 57.69,30.42 57.69,27.09 v58.33,26.45
  Bottom 0.305: IC1.61 45.56,28.43 48.16,25.82 56.42,25.82 57.05,26.45 v58.33,26.45
N$31  (via drill 0.41)
  Top 0.254: IC2.19 56.59,30.72 57.05,30.26 57.05,26.14 v57.69,25.5
  Bottom 0.305: IC1.62 45.26,27.77 47.85,25.18 56.74,25.18 57.05,25.5 v57.69,25.5
N$32  (via drill 0.41)
  Top 0.254: v38.32,32.17 47.53,32.17 49.7,30 IC2.29
  Bottom 0.254: IC1.63 38.92,27.12 38.64,27.41 38.64,31.85 v38.32,32.17
N$33  (via drill 0.41)
  Top 0.254: v37.85,31.06 47.69,31.06 49.24,29.5 IC2.30
  Bottom 0.254: IC1.64 38.62,26.48 37.85,27.25 v37.85,31.06
N$34  (via drill 0.41)
  Top 0.254: v26.26,32.48 32.92,32.48 34.83,34.71 37.05,34.71 38.01,33.76 47.05,33.76 48.32,35.02 51.34,35.02 51.98,35.66 53.88,35.66 54.59,34.95 IC2.23
  Top 0.305: v26.26,32.48 25.94,32.17 25.94,29.63 27.21,28.36 27.21,18.83 25.62,17.24 25.62,14.39 v24.99,13.75
  Bottom 0.254: IC1.26 26.1,32.33 v26.26,32.48
  Bottom 0.305: IC1.100 25.64,14.4 v24.99,13.75
N$35  (via drill 0.41)
  Top 0.254: v33.88,18.36 38.8,18.36 40.94,20.5 IC2.48
  Bottom 0.305: IC1.89 33.27,17.7 v33.88,18.36
N$36  (via drill 0.41)
  Top 0.254: v32.61,19.15 38.64,19.15 40.49,21 IC2.47
  Bottom 0.305: IC1.90 32.62,17.55 32.61,17.88 v32.61,19.15
N$37  (via drill 0.41)
  Top 0.254: v31.97,20.74 38.32,20.74 39.59,22 IC2.45
  Bottom 0.305: IC1.92 31.31,20.08 v31.97,20.74
N$38  (via drill 0.41)
  Top 0.254: v26.26,10.42 30.86,10.42 31.66,9.62 34.51,9.62 37.69,12.8 40.86,12.8 41.5,13.44 45.94,13.44 47.21,12.16 57.69,12.16 59.91,14.39 | IC2.83 65.98,23 65.31,22.32 v65.31,21.85
  Top 0.305: 59.91,14.39 v59.91,14.55
  Bottom 0.305: IC1.91 31.97,13.11 30.7,11.85 27.69,11.85 v26.26,10.42 | v65.31,21.85 62.29,21.85 59.91,19.47 v59.91,14.55
N$39  (via drill 0.41)
  Top 0.254: v31.66,33.28 32.45,33.28 35.78,36.93 58.64,36.93 60.87,34.71 61.18,34.71 61.59,34.3 IC2.9
  Bottom 0.305: IC1.93 30.66,27.05 31.66,28.04 v31.66,33.28
N$40  (via drill 0.41)
  Top 0.254: IC2.63 59.59,16.29 56.74,13.44 47.85,13.44 46.58,14.71 40.86,14.71 40.23,14.07 37.05,14.07 33.88,10.89 32.29,10.89 31.34,11.85 23.4,11.85 22.77,12.48 v22.13,12.48
  Bottom 0.305: IC1.3 22.58,17.38 22.45,17.24 22.45,12.8 v22.13,12.48
N$41  (via drill 0.41)
  Top 0.254: IC2.64 60.09,15.84 57.05,12.8 47.53,12.8 46.26,14.07 41.18,14.07 40.55,13.44 37.37,13.44 34.2,10.26 31.97,10.26 31.02,11.21 22.13,11.21 v20.86,12.48
  Bottom 0.305: IC1.4 22.27,18.02 21.81,17.56 21.81,13.44 v20.86,12.48
N$42  (via drill 0.41)
  Top 0.254: IC2.59 57.59,15.24 56.42,14.07 48.16,14.07 46.9,15.34 40.55,15.34 39.91,14.71 36.73,14.71 33.56,11.53 32.61,11.53 31.66,12.48 23.72,12.48 22.45,13.75 v20.86,13.75
  Bottom 0.305: IC1.5 21.97,18.68 21.18,17.88 21.18,14.07 v20.86,13.75
N$43
  Bottom 0.305: IC1.84 36.52,13.34 37.69,12.16 38.96,12.16 39.27,11.85 R5.2 39.27,10.89
N$44
  Bottom 0.305: IC1.6 21.67,19.32 20.54,18.2 20.54,15.02 18.95,13.44 R1.1
N$45
  Bottom 0.305: IC1.7 21.37,19.98 19.91,18.52 19.91,16.29 18.95,15.34 R2.1 17.68,15.34
N$46
  Bottom 0.305: IC1.8 21.07,20.62 19.27,18.83 19.27,17.56 18.95,17.24 R3.1
N$47
  Bottom 0.305: R4.1 21.68,33.25 21.96,32.98 IC1.27
N$48
  Bottom 0.305: R6.2 21.63,28.81 22.55,29.73 IC1.22
N$49
  Bottom 0.305: IC1.79 41.7,16.73 42.21,16.21 R30.1
N$50
  Bottom 0.305: R55.1 74.83,15.18 73.81,14.16 Q3.C
N$51
  Bottom 0.305: R7.2 21.47,29.92 21.93,30.38 IC1.23
N$52
  Bottom 0.305: R8.2 IC1.24
N$53
  Bottom 0.305: R10.2 32.61,39.79 32.62,39.78 IC1.41
N$54
  Bottom 0.305: IC1.43 33.91,37.92 34.83,38.84 R11.2
N$55
  Bottom 0.305: IC1.25 21.99,31.68 21.52,32.14 R9.2
N$56
  Bottom 0.305: IC3.1 25.62,43.28 | 25.62,43.28 R18.2 | 25.62,43.28 R17.1
N$58
  Bottom 0.305: C1.2 15.78,23.2 18.32,23.2 18.32,23.28 | 18.32,23.28 Q1.2 | IC1.11 19.02,22.57 18.32,23.28
N$59
  Bottom 0.305: C2.2 15.78,21.29 18.32,21.29 | Q1.1 18.32,21.29 | 18.32,21.29 18.32,21.37 18.87,21.93 IC1.10
N$60
  Bottom 0.305: IC1.87 34.56,12.54 34.2,12.16 R12.1 34.2,10.89
N$61
  Top 0.305: IC12.4 55.8,8.98 56.1,8.67 60.55,8.67 60.87,8.36 C25.1
N$63
  Bottom 0.305: JP3.2 20.23,36.93 19.91,37.25 19.91,38.84 19.27,39.47 IC3.5 15.94,39.47 15.62,39.15 R16.1
N$64
  Top 0.305: LED1.A 90.81,40.33 91.34,39.79 D4.AR
  Bottom 0.305: R14.1 90.79,40.34 91.34,39.79 D4.AR D5.AR
N$65
  Top 0.305: LED2.A 90.81,44.33 91.34,44.87 D4.AG
  Bottom 0.305: R15.1 90.79,44.31 91.34,44.87 D4.AG D5.AG
N$66
  Bottom 0.305: IC1.17 14.53,26.48 13.56,25.5 12.13,25.5 | 12.13,25.5 12.12,25.5 | X1.3 12.13,25.5
N$67  (via drill 0.41)
  Top 0.305: 81.19,36.3 R50.1 81.19,35.5 | R53.1 81.19,35.5 | 81.19,35.5 v82.61,35.5
  Bottom 0.305: v82.61,35.5 87.53,35.5 90.71,32.33 90.71,27.72 D2.A
N$75
  Top 0.254: IC2.8 62.09,34.67 61.74,35.02 R26.2
N$76
  Top 0.305: R34.2 87.85,19.15 87.84,19.13 IC5.4
N$77
  Top 0.305: IC10.5 78.01,37.88 78.33,38.2 R49.1 81.19,38.2 R50.2
N$78
  Top 0.305: IC6.4 87.07,21.99 87.38,21.69 R37.2
N$79
  Top 0.305: IC10.6 76.74,33.44 77.06,33.76 R51.2 R52.1
N$80
  Bottom 0.406: R47.1 81.19,27.72 | R47.1 81.19,26.45 | 81.19,26.45 R46.2 | R47.1 80.07,27.64 79.99,27.72 79.12,27.72 79.12,27.73 IC9.3 | 81.19,26.45 81.19,25.18 82.61,25.18 83.09,24.71 D3.A
N$81
  Bottom 0.406: R57.1 Q2.3
N$82
  Top 0.305: IC7.4 87.07,26.12 87.38,25.82 R40.2
N$83
  Bottom 0.406: IC9.1 79.16,30.14 79.04,30.26 R44.1 R45.2
N$84
  Top 0.305: IC8.4 87.07,32.15 87.38,31.85 87.85,31.85 | 87.85,31.85 | 87.85,31.85 R43.2
N$86
  Bottom 0.305: Q3.B 70.71,17.32 70.55,17.48 70.55,18.52 | R57.2 70.55,21.05 70.55,18.52 | 70.55,18.52 R56.1
  Bottom 0.406: R56.1 70.63,18.44
N$87
  Bottom 0.406: R65.2 75.95,29.71 76.03,29.63 76.82,29.63 76.82,29.62 IC9.6
N$89
  Bottom 0.406: R55.2 74.83,18.52 77.06,18.52 | 77.06,18.52 R54.2 | 77.06,18.52 78.33,18.52 78.52,18.7 79.36,18.7 79.36,18.67 IC11.4
N$90
  Top 0.305: 85.63,27.72 85.61,27.74 | 85.63,23.91 85.61,23.93 | 85.63,20.1 85.61,20.12 | IC5.1 85.63,20.43 85.63,20.42 | IC6.1 85.63,23.29 85.63,23.28 | IC7.1 85.63,27.42 85.63,27.41 | 85.31,33.45 85.38,33.45 85.63,33.2 85.63,29.79 R13.1 | 85.31,33.45 IC8.1 | 85.31,33.45 85.31,33.44
  Top 0.406: 85.63,29.79 85.63,27.72 85.63,27.41 85.63,23.91 85.63,23.28 85.63,20.42 85.63,20.1 Q4.3 | 85.63,29.79
N$92
  Top 0.305: IC10.3 76.74,24.63 76.5,24.39 R60.1 R63.2
N$93
  Top 0.305: R62.2 75.79,21.37 75.47,21.69 IC10.2 75.47,27.41 75.79,27.72 79.76,27.72 R61.1
RST
  Bottom 0.305: IC1.77 43.87,18.02 44.67,18.83 45.62,18.83 R31.1 46.5,18.91 46.9,18.52 48.48,18.52 C5.+
SERIAL_NUMBER
  Bottom 0.305: IC1.86 35.22,12.57 35.47,12.32 35.47,9.94 | 35.47,9.94 35.47,9.31 35.78,8.99 36.73,8.99 R27.1 | 35.47,9.94 30.7,9.94 30.07,9.31 IC4.2 27.05,9.31 26.42,8.67 25.3,8.67 24.99,8.36 IC14.1
SLOE_INT  (via drill 0.41)
  Top 0.305: 74.2,24.55 IC10.1 | 74.2,24.55 74.44,24.31 R60.2 | R59.1 v72.3,24.55 74.2,24.55
  Bottom 0.305: IC1.69 41.55,23.23 42.13,22.64 69.12,22.64 71.03,24.55 v72.3,24.55
TCK
  Top 0.406: 90.23,26.77 94.84,26.77 | 94.84,26.77 100.08,26.77 SV2.6 | R39.2 90.23,27.72 90.23,26.77 | R40.1 90.23,25.82 90.23,26.77 | 94.84,26.77 SV1.6
TCK_INT  (via drill 0.41)
  Top 0.254: IC2.66 61.09,14.79 62.77,13.12
  Top 0.305: IC7.2 v83.57,26.77 83.09,26.77 82.77,26.45 82.77,23.28 82.14,22.64 82.14,20.74 81.5,20.1 81.5,14.23 80.39,13.12 62.77,13.12
  Bottom 0.305: 85,26.77 R38.1 v83.57,26.77
TDI
  Top 0.305: 90.23,23.59
  Top 0.406: R36.2 90.23,23.59 90.23,21.69 | R37.1 90.23,21.69 | 90.23,21.69 94.84,21.69 | 94.84,21.69 100.08,21.69 SV2.10 | 94.84,21.69 SV1.10
TDI_INT  (via drill 0.41)
  Top 0.254: IC2.68 62.09,15.86 v62.77,15.18
  Top 0.305: IC6.2 v83.57,22.64 83.09,22.64 82.77,22.32 82.77,20.42 82.14,19.79 82.14,13.91 80.71,12.48 62.29,12.48 v61.18,13.59
  Bottom 0.305: v83.57,22.64 R35.1 | v61.18,13.59 v62.77,15.18
TDO
  Bottom 0.406: SV2.8 100.08,24.23 94.84,24.23 | 94.84,24.23 91.82,24.23 91.34,24.71 88.88,24.71 | 88.88,24.71 | D3.C 88.88,24.71 | 94.84,24.23 SV1.8
TDO_INT  (via drill 0.41)
  Top 0.254: IC2.27 50.6,31 50.39,31.21 50.39,32.17 50.7,32.48 v50.7,33.12
  Top 0.305: v68.17,36.3 v71.03,33.44
  Bottom 0.305: IC9.5 73.56,28.68 73.25,28.99 73.25,31.21 v71.03,33.44 | v50.7,33.12 51.34,32.48 64.99,32.48 68.17,35.66 v68.17,36.3 | v68.17,36.3
TMS
  Top 0.406: R42.2 90.23,33.76 90.23,31.85 | R43.1 90.23,31.85 | 90.23,31.85 | 90.23,31.85 94.84,31.85 | 94.84,31.85 100.08,31.85 SV2.4 | SV2.4 | 94.84,31.85 SV1.4
TMS_INT  (via drill 0.41)
  Top 0.254: IC2.67 61.59,15.24 63.09,13.75
  Top 0.305: IC8.2 v83.57,32.8 83.09,32.8 82.77,32.48 82.77,30.9 83.57,30.1 83.57,29.31 82.77,28.52 82.77,27.41 82.14,26.77 82.14,23.59 81.5,22.96 81.5,21.05 80.87,20.42 80.87,14.55 80.07,13.75 63.09,13.75
  Bottom 0.305: v83.57,32.8 R41.1
USB_SCL
  Bottom 0.305: IC1.29 18.43,34.27 16.73,35.98 14.19,35.98 13.88,36.3 13.88,40.74 14.19,41.06 R28.1 15.62,41.06 15.94,40.74 IC3.6
USB_SDA
  Bottom 0.305: IC1.30 19.05,34.92 18.64,35.34 JP3.1 16.89,36.93 16.57,37.25 R29.1
V+  (via drill 0.61)
  Top 0.305: IC8.5 87.07,33.45 87.38,33.76 R42.1 89.12,33.76 | IC7.5 87.07,27.42 87.38,27.72 R39.1 89.12,27.72 | 87.85,23.59 | 87.85,23.59 R36.1 | 87.38,23.59 87.85,23.59 | IC5.5 89.12,20.43 89.12,20.42 | 89.12,29.79 R13.2 | 89.12,29.79 | IC6.5 87.07,23.29 87.38,23.59 | 89.12,23.59 87.38,23.59
  Top 0.406: v89.12,17.4 89.12,20.42 89.12,23.59 89.12,27.72 89.12,29.79 89.12,33.76 89.12,36.93 D1.C
  Top 0.813: D1.C 91.5,36.93 | 91.5,36.93 v91.5,37.56 | 91.5,36.93 v91.5,36.3
  Bottom 0.305: Q3.E 72.61,17.32 72.69,17.4 72.77,17.4 72.77,18.52 R56.2
  Bottom 0.406: C22.1 IC11.5 81.18,18.68 81.19,18.67 81.19,17.4 | 80.23,17.4 IC11.2 | 72.77,17.4 80.23,17.4 | 72.77,17.4 | 80.23,17.4 81.19,17.4 | 81.19,17.4 v89.12,17.4
  Bottom 0.813: 91.5,36.93 R32.1 | 91.5,36.93 | v91.5,37.56 91.5,36.93 | v91.5,36.3 91.5,36.93
VREF
  Bottom 0.406: SV2.2
  Bottom 0.813: 94.04,36.93 | 94.04,36.93 R32.2 94.02,36.87 94.04,36.85 94.04,35.1 94.84,34.31 SV1.2 | 94.04,36.93 100.26,36.93 101.35,35.84 SV2.2 | SV2.2
VREF_ENABLE  (via drill 0.41)
  Top 0.305: 81.19,32.8 R53.2 81.98,31.93 81.98,29.71 | 81.98,29.71 v82.77,29.71 | 81.98,29.71 81.98,27.56 81.5,27.09 81.5,25.34 80.39,24.23 80.39,23.28 | 80.39,23.28 80.39,20.9 80.23,20.74 80.23,15.18 v79.6,14.55 | 80.39,23.28 R63.1
  Bottom 0.305: 81.19,15.82 81.19,15.18 80.55,14.55 v79.6,14.55 | v82.77,29.71 R47.2
  Bottom 0.406: 81.19,15.82 81.18,15.82 IC11.1

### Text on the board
Top: Xilinx-USB-JTAG | V1.04 Jan. 2010 | MockUp
Bottom: Xilinx-USB-JTAG | V1.04 Jan. 2010 | MockUp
